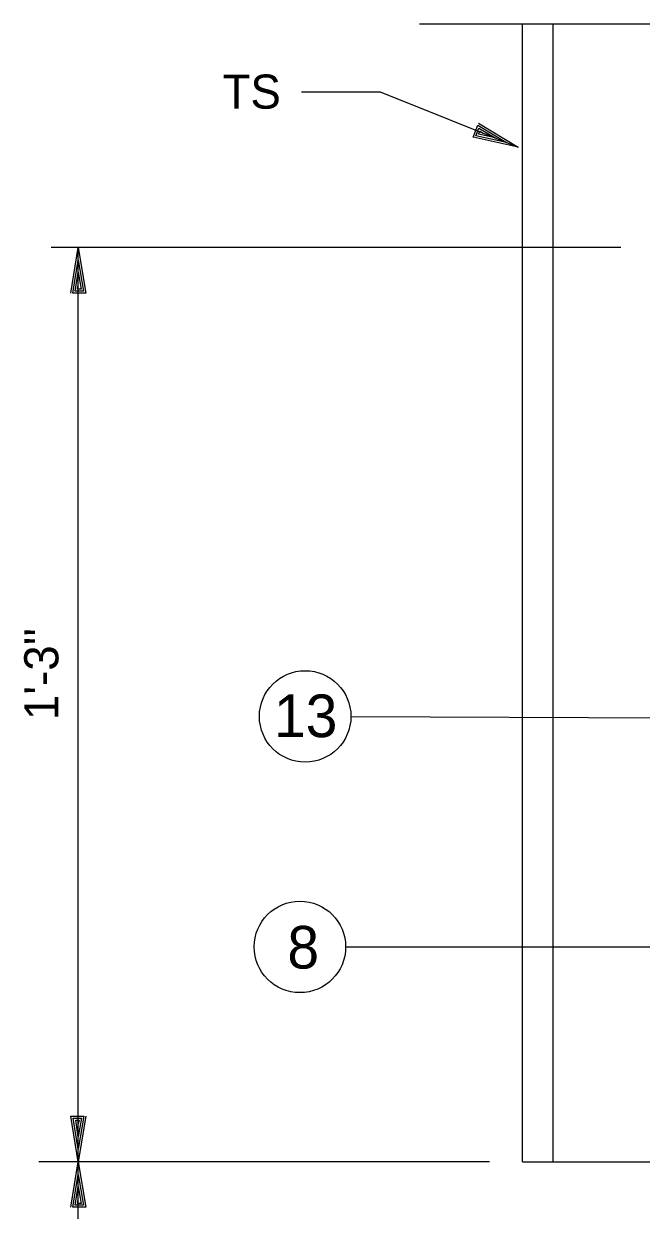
# Model space of a CAD drawing. Extents: x -0.2 to 13.5, y -0.2 to 9.5.
# Drawn here: x 10.074 to 10.918, y 4.312 to 5.935 of the extents above; entities that cross this region are included whole.
import ezdxf

# ---------------------------------------------------------------- set-up
doc = ezdxf.new("R2010")
doc.units = 0
for name, color, linetype in [('Level 2', 7, 'Continuous'), ('Level 3', 7, 'Continuous'), ('Level 50', 7, 'Continuous')]:
    doc.layers.add(name, color=color, linetype=linetype)

msp = doc.modelspace()

# ---------------------------------------------------------------- linework, layer by layer
at = {"layer": 'Level 2'}
for p, q in [((10.6149, 5.9346), (10.9944, 5.9346)), ((10.7555, 4.3787), (10.7555, 5.9346)), ((10.7972, 4.3787), (10.7972, 5.9346)), ((10.1487, 4.3787), (10.1487, 5.6287)), ((10.1487, 3.8371), (10.1487, 4.3787)), ((10.7555, 4.3787), (11.1462, 4.3787))]:
    msp.add_line(p, q, dxfattribs=at)
at = {"layer": 'Level 3'}
for p, q in [((10.7335, 5.7722), (10.7335, 5.7722)), ((10.7496, 5.7658), (10.7496, 5.7658)), ((10.8896, 5.6287), (10.1115, 5.6287)), ((10.1487, 5.6287), (10.1487, 5.6287)), ((10.1487, 5.6114), (10.1487, 5.6114)), ((10.5211, 4.9872), (11.138, 4.9849)), ((10.5139, 4.6724), (11.0762, 4.6724)), ((10.1487, 4.3961), (10.1487, 4.3961)), ((10.7102, 4.3787), (10.0949, 4.3787)), ((10.1487, 4.3787), (10.1487, 4.3787))]:
    msp.add_line(p, q, dxfattribs=at)
for points in [[(10.4538, 5.8413), (10.561, 5.8413), (10.7496, 5.7658)], [(10.6955, 5.7986), (10.7496, 5.7658), (10.6879, 5.7794), (10.6944, 5.7958), (10.7335, 5.7722), (10.6916, 5.7815), (10.6958, 5.792), (10.718, 5.7784), (10.6953, 5.7836), (10.697, 5.7879), (10.7019, 5.7849)], [(10.1384, 5.5664), (10.1487, 5.6287), (10.1591, 5.5664), (10.1414, 5.5664), (10.1487, 5.6114), (10.1557, 5.5691), (10.1444, 5.5691), (10.1487, 5.5947), (10.1524, 5.5717), (10.1477, 5.5717), (10.1487, 5.5774)], [(10.1591, 4.4411), (10.1487, 4.3787), (10.1384, 4.4411), (10.1561, 4.4411), (10.1487, 4.3961), (10.1417, 4.4384), (10.1531, 4.4384), (10.1487, 4.4127), (10.1451, 4.4357), (10.1497, 4.4357), (10.1487, 4.4301)]]:
    msp.add_lwpolyline(points, dxfattribs=at)
for centre in [(10.4586, 4.9875), (10.4514, 4.6724)]:
    msp.add_circle(centre, 0.0625, dxfattribs=at)
at = {"layer": 'Level 50'}
for p, q in [((10.1487, 4.3787), (10.1487, 4.3787)), ((10.1487, 4.3614), (10.1487, 4.3614))]:
    msp.add_line(p, q, dxfattribs=at)
msp.add_lwpolyline([(10.1384, 4.3164), (10.1487, 4.3787), (10.1591, 4.3164), (10.1414, 4.3164), (10.1487, 4.3614), (10.1557, 4.3191), (10.1444, 4.3191), (10.1487, 4.3447), (10.1524, 4.3217), (10.1477, 4.3217), (10.1487, 4.3274)], dxfattribs=at)

# ---------------------------------------------------------------- texts
at = {"layer": 'Level 3'}
for s, height, p in [('TS', 0.04667, (10.3457, 5.8184)), ('13', 0.05833, (10.4159, 4.9592)), ('8', 0.0583, (10.4343, 4.6428))]:
    msp.add_text(s, height=height, dxfattribs=at).set_placement(p)
msp.add_text("1'-3''", height=0.04667, rotation=90, dxfattribs=at).set_placement((10.1215, 4.9826))

doc.saveas('drawing.dxf')
